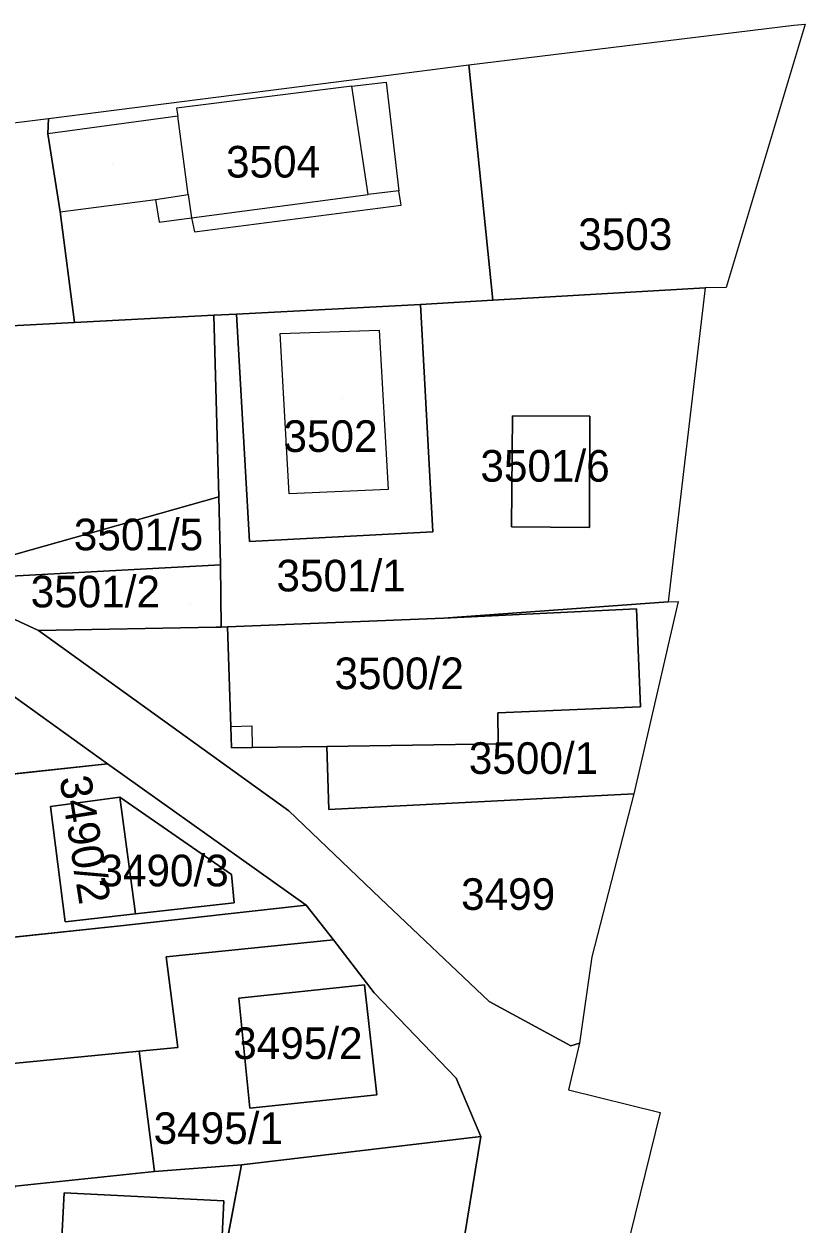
# Model space of a CAD drawing. Extents: x -262657 to -261595, y -1238015 to -1237156.
# Drawn here: x -262117.9 to -262068.5, y -1237493.9 to -1237418 of the extents above; entities that cross this region are included whole.
import ezdxf

# ---------------------------------------------------------------- set-up
doc = ezdxf.new("R2010")
doc.units = 0
for name, color, linetype in [('body_kn', 7, 'Continuous'), ('kladpar_druhypozemkov', 7, 'Continuous'), ('kladpar_hranice', 7, 'Continuous'), ('kladpar_parcelnecisla', 7, 'Continuous'), ('kladpar_plochy', 7, 'Continuous'), ('zappar_hrandruhpozemk', 7, 'Continuous')]:
    doc.layers.add(name, color=color, linetype=linetype)

msp = doc.modelspace()

# ---------------------------------------------------------------- linework, layer by layer
at = {"layer": 'body_kn'}
for p, q in [((-262069.23, -1237418.11), (-262069.23, -1237418.11)), ((-262068.53, -1237418.03), (-262068.53, -1237418.03)), ((-262090.13, -1237420.66), (-262090.13, -1237420.66)), ((-262089.8, -1237420.62), (-262089.8, -1237420.62)), ((-262089.8, -1237420.62), (-262089.8, -1237420.62)), ((-262095.05, -1237421.28), (-262095.05, -1237421.28)), ((-262097.19, -1237421.97), (-262097.19, -1237421.97)), ((-262097.19, -1237421.97), (-262097.19, -1237421.97)), ((-262095.02, -1237421.7), (-262095.02, -1237421.7)), ((-262108.29, -1237423.36), (-262108.29, -1237423.36)), ((-262116.37, -1237424), (-262116.37, -1237424)), ((-262108.2, -1237423.86), (-262108.2, -1237423.86)), ((-262116.41, -1237424.98), (-262116.41, -1237424.98)), ((-262107.54, -1237428.82), (-262107.54, -1237428.82)), ((-262107.54, -1237428.82), (-262107.54, -1237428.82)), ((-262096.16, -1237428.82), (-262096.16, -1237428.82)), ((-262096.16, -1237428.82), (-262096.16, -1237428.82)), ((-262094.21, -1237428.57), (-262094.21, -1237428.57)), ((-262109.62, -1237429.12), (-262109.62, -1237429.12)), ((-262109.62, -1237429.12), (-262109.62, -1237429.12)), ((-262094.07, -1237429.48), (-262094.07, -1237429.48)), ((-262115.63, -1237429.9), (-262115.63, -1237429.9)), ((-262115.63, -1237429.9), (-262115.63, -1237429.9)), ((-262109.37, -1237430.57), (-262109.37, -1237430.57)), ((-262107.34, -1237430.29), (-262107.34, -1237430.29)), ((-262107.34, -1237430.29), (-262107.34, -1237430.29)), ((-262107.15, -1237431.18), (-262107.15, -1237431.18)), ((-262074.85, -1237434.72), (-262074.85, -1237434.72)), ((-262073.52, -1237434.7), (-262073.52, -1237434.7)), ((-262092.84, -1237435.77), (-262092.84, -1237435.77)), ((-262092.84, -1237435.77), (-262092.84, -1237435.77)), ((-262088.28, -1237435.49), (-262088.28, -1237435.49)), ((-262105.91, -1237436.45), (-262105.91, -1237436.45)), ((-262104.48, -1237436.37), (-262104.48, -1237436.37)), ((-262114.74, -1237436.9), (-262114.74, -1237436.9)), ((-262095.46, -1237437.4), (-262095.46, -1237437.4)), ((-262101.73, -1237437.61), (-262101.73, -1237437.61)), ((-262101.73, -1237437.61), (-262101.73, -1237437.61)), ((-262087.04, -1237442.8), (-262087.04, -1237442.8)), ((-262087.04, -1237442.8), (-262087.04, -1237442.8)), ((-262082.14, -1237442.83), (-262082.14, -1237442.83)), ((-262105.6, -1237447.92), (-262105.6, -1237447.92)), ((-262101.16, -1237447.74), (-262101.16, -1237447.74)), ((-262094.9, -1237447.46), (-262094.9, -1237447.46)), ((-262092.06, -1237450.15), (-262092.06, -1237450.15)), ((-262087.09, -1237449.83), (-262087.09, -1237449.83)), ((-262082.17, -1237449.86), (-262082.17, -1237449.86)), ((-262103.67, -1237450.75), (-262103.67, -1237450.75)), ((-262105.49, -1237452.24), (-262105.49, -1237452.24)), ((-262077.18, -1237454.57), (-262077.18, -1237454.57)), ((-262077.18, -1237454.57), (-262077.18, -1237454.57)), ((-262076.55, -1237454.54), (-262076.55, -1237454.54)), ((-262091.39, -1237455.6), (-262091.39, -1237455.6)), ((-262079.19, -1237455.01), (-262079.19, -1237455.01)), ((-262117.01, -1237456.38), (-262117.01, -1237456.38)), ((-262117.01, -1237456.38), (-262117.01, -1237456.38)), ((-262105.78, -1237456.17), (-262105.78, -1237456.17)), ((-262105.45, -1237456.17), (-262105.45, -1237456.17)), ((-262105.06, -1237456.15), (-262105.06, -1237456.15)), ((-262105.06, -1237456.15), (-262105.06, -1237456.15)), ((-262087.96, -1237461.59), (-262087.96, -1237461.59)), ((-262078.94, -1237461.21), (-262078.94, -1237461.21)), ((-262104.85, -1237462.46), (-262104.85, -1237462.46)), ((-262104.85, -1237462.46), (-262104.85, -1237462.46)), ((-262103.52, -1237462.42), (-262103.52, -1237462.42)), ((-262104.81, -1237463.8), (-262104.81, -1237463.8)), ((-262103.5, -1237463.78), (-262103.5, -1237463.78)), ((-262098.78, -1237463.71), (-262098.78, -1237463.71)), ((-262087.93, -1237463.54), (-262087.93, -1237463.54)), ((-262112.65, -1237464.82), (-262112.65, -1237464.82)), ((-262111.86, -1237466.92), (-262111.86, -1237466.92)), ((-262111.86, -1237466.92), (-262111.86, -1237466.92)), ((-262079.35, -1237466.7), (-262079.35, -1237466.7)), ((-262079.35, -1237466.7), (-262079.35, -1237466.7)), ((-262116.25, -1237467.51), (-262116.25, -1237467.51)), ((-262116.25, -1237467.51), (-262116.25, -1237467.51)), ((-262098.64, -1237467.71), (-262098.64, -1237467.71)), ((-262101.17, -1237467.78), (-262101.17, -1237467.78)), ((-262104.81, -1237471.82), (-262104.81, -1237471.82)), ((-262104.63, -1237473.6), (-262104.63, -1237473.6)), ((-262100.07, -1237473.74), (-262100.07, -1237473.74)), ((-262100.07, -1237473.74), (-262100.07, -1237473.74)), ((-262095.4, -1237473.3), (-262095.4, -1237473.3)), ((-262110.87, -1237474.3), (-262110.87, -1237474.3)), ((-262115.33, -1237474.8), (-262115.33, -1237474.8)), ((-262111.63, -1237475.04), (-262111.63, -1237475.04)), ((-262098.36, -1237475.95), (-262098.36, -1237475.95)), ((-262098.36, -1237475.95), (-262098.36, -1237475.95)), ((-262108.93, -1237477.01), (-262108.93, -1237477.01)), ((-262082.01, -1237477.02), (-262082.01, -1237477.02)), ((-262096.39, -1237478.78), (-262096.39, -1237478.78)), ((-262104.34, -1237479.64), (-262104.34, -1237479.64)), ((-262095.77, -1237479.3), (-262095.77, -1237479.3)), ((-262088.51, -1237479.84), (-262088.51, -1237479.84)), ((-262108.19, -1237482.75), (-262108.19, -1237482.75)), ((-262083.34, -1237482.64), (-262083.34, -1237482.64)), ((-262082.79, -1237482.48), (-262082.79, -1237482.48)), ((-262110.64, -1237482.99), (-262110.64, -1237482.99)), ((-262110.64, -1237482.99), (-262110.64, -1237482.99)), ((-262090.6, -1237484.7), (-262090.6, -1237484.7)), ((-262095.61, -1237485.75), (-262095.61, -1237485.75)), ((-262083.48, -1237485.42), (-262083.48, -1237485.42)), ((-262103.64, -1237486.58), (-262103.64, -1237486.58)), ((-262103.64, -1237486.58), (-262103.64, -1237486.58)), ((-262077.7, -1237486.87), (-262077.7, -1237486.87)), ((-262089.04, -1237488.37), (-262089.04, -1237488.37)), ((-262104.18, -1237490.18), (-262104.18, -1237490.18)), ((-262109.68, -1237490.6), (-262109.68, -1237490.6)), ((-262115.39, -1237491.95), (-262115.39, -1237491.95)), ((-262115.39, -1237491.95), (-262115.39, -1237491.95)), ((-262105.28, -1237492.44), (-262105.28, -1237492.44)), ((-262079.28, -1237493.28), (-262079.28, -1237493.28))]:
    msp.add_line(p, q, dxfattribs=at)
at = {"layer": 'kladpar_druhypozemkov'}
for p, q in [((-262102.06, -1237425.79), (-262102.06, -1237425.79)), ((-262112.32, -1237426.86), (-262112.32, -1237426.86)), ((-262079.63, -1237430.09), (-262079.63, -1237430.09)), ((-262097.78, -1237441.71), (-262097.78, -1237441.71)), ((-262084.64, -1237445.3), (-262084.64, -1237445.3)), ((-262107.55, -1237449.98), (-262107.55, -1237449.98)), ((-262098.05, -1237452.19), (-262098.05, -1237452.19)), ((-262107.4, -1237454.65), (-262107.4, -1237454.65)), ((-262093, -1237457.72), (-262093, -1237457.72)), ((-262084.88, -1237463.58), (-262084.88, -1237463.58)), ((-262113.06, -1237470.35), (-262113.06, -1237470.35)), ((-262108.54, -1237470.73), (-262108.54, -1237470.73)), ((-262087.23, -1237472.24), (-262087.23, -1237472.24)), ((-262099.72, -1237482.04), (-262099.72, -1237482.04)), ((-262105.41, -1237486.92), (-262105.41, -1237486.92))]:
    msp.add_line(p, q, dxfattribs=at)
at = {"layer": 'kladpar_hranice'}
for points in [[(-262089.8, -1237420.62), (-262069.23, -1237418.11), (-262068.53, -1237418.03), (-262073.52, -1237434.7), (-262074.85, -1237434.72), (-262088.28, -1237435.49), (-262089.8, -1237420.62)], [(-262092.84, -1237435.77), (-262104.48, -1237436.37), (-262105.91, -1237436.45), (-262114.74, -1237436.9), (-262115.63, -1237429.9), (-262116.41, -1237424.98), (-262116.37, -1237424), (-262095.05, -1237421.28), (-262090.13, -1237420.66), (-262089.8, -1237420.62), (-262088.28, -1237435.49), (-262092.84, -1237435.77)], [(-262173.41, -1237431.09), (-262116.37, -1237424), (-262116.41, -1237424.98), (-262115.63, -1237429.9), (-262114.74, -1237436.9), (-262145.51, -1237438.52), (-262171.89, -1237439.97), (-262172.3, -1237439.99), (-262173.41, -1237431.09)], [(-262074.85, -1237434.72), (-262077.18, -1237454.57), (-262091.39, -1237455.6), (-262105.06, -1237456.15), (-262105.45, -1237456.17), (-262105.49, -1237452.24), (-262105.6, -1237447.92), (-262105.91, -1237436.45), (-262104.48, -1237436.37), (-262103.67, -1237450.75), (-262092.06, -1237450.15), (-262092.84, -1237435.77)], [(-262092.84, -1237435.77), (-262088.28, -1237435.49), (-262074.85, -1237434.72)], [(-262092.84, -1237435.77), (-262092.06, -1237450.15), (-262103.67, -1237450.75), (-262104.48, -1237436.37), (-262092.84, -1237435.77)], [(-262133.73, -1237451.77), (-262144.2, -1237451.94), (-262145.51, -1237438.52), (-262114.74, -1237436.9), (-262105.91, -1237436.45), (-262105.6, -1237447.92), (-262118.45, -1237451.55), (-262133.73, -1237451.77)], [(-262087.04, -1237442.8), (-262082.14, -1237442.83), (-262082.17, -1237449.86), (-262087.09, -1237449.83), (-262087.04, -1237442.8)], [(-262082.14, -1237442.83), (-262087.04, -1237442.8), (-262087.09, -1237449.83), (-262082.17, -1237449.86), (-262082.14, -1237442.83)], [(-262123.85, -1237453.21), (-262133.73, -1237451.77), (-262118.45, -1237451.55), (-262105.6, -1237447.92), (-262105.49, -1237452.24), (-262123.85, -1237453.21)], [(-262172.23, -1237452.72), (-262144.2, -1237451.94), (-262133.73, -1237451.77), (-262123.85, -1237453.21), (-262117.01, -1237456.38), (-262101.17, -1237467.78), (-262095.4, -1237473.3), (-262088.51, -1237479.84), (-262083.34, -1237482.64), (-262082.79, -1237482.48), (-262083.48, -1237485.42), (-262077.7, -1237486.87), (-262079.28, -1237493.28), (-262079.83, -1237495.53)], [(-262117.01, -1237456.38), (-262123.85, -1237453.21), (-262105.49, -1237452.24), (-262105.45, -1237456.17), (-262105.78, -1237456.17), (-262117.01, -1237456.38)], [(-262077.18, -1237454.57), (-262076.55, -1237454.54), (-262079.35, -1237466.7), (-262098.64, -1237467.71), (-262098.78, -1237463.71), (-262087.93, -1237463.54), (-262087.96, -1237461.59), (-262078.94, -1237461.21), (-262079.19, -1237455.01), (-262091.39, -1237455.6), (-262077.18, -1237454.57)], [(-262090.96, -1237500.11), (-262089.04, -1237488.37), (-262090.6, -1237484.7), (-262095.77, -1237479.3), (-262098.36, -1237475.95), (-262100.07, -1237473.74), (-262112.65, -1237464.82), (-262118.96, -1237460.26), (-262120.3, -1237459.49), (-262124.74, -1237457.28), (-262137.3, -1237455.41), (-262166.33, -1237456.32)], [(-262105.06, -1237456.15), (-262091.39, -1237455.6), (-262079.19, -1237455.01), (-262078.94, -1237461.21), (-262087.96, -1237461.59), (-262087.93, -1237463.54), (-262098.78, -1237463.71), (-262103.5, -1237463.78), (-262104.81, -1237463.8), (-262104.85, -1237462.46), (-262105.06, -1237456.15)], [(-262079.35, -1237466.7), (-262082.01, -1237477.02), (-262082.79, -1237482.48), (-262083.34, -1237482.64), (-262088.51, -1237479.84), (-262095.4, -1237473.3), (-262101.17, -1237467.78), (-262117.01, -1237456.38), (-262105.78, -1237456.17), (-262105.45, -1237456.17), (-262105.06, -1237456.15), (-262104.85, -1237462.46), (-262104.81, -1237463.8), (-262103.5, -1237463.78), (-262098.78, -1237463.71), (-262098.64, -1237467.71), (-262079.35, -1237466.7)], [(-262143.93, -1237461.51), (-262120.3, -1237459.49), (-262118.96, -1237460.26), (-262112.65, -1237464.82), (-262128.64, -1237466.53), (-262127.67, -1237476.36), (-262127.63, -1237476.72), (-262135.5, -1237477.53), (-262135.51, -1237477.18), (-262135.55, -1237475.84), (-262137.27, -1237475.95), (-262138.13, -1237467.57), (-262143.12, -1237468.01), (-262143.93, -1237461.51)], [(-262128.64, -1237466.53), (-262112.65, -1237464.82), (-262100.07, -1237473.74)], [(-262100.07, -1237473.74), (-262111.63, -1237475.04), (-262121.33, -1237476.07), (-262127.63, -1237476.72), (-262127.67, -1237476.36), (-262128.64, -1237466.53)], [(-262116.25, -1237467.51), (-262111.86, -1237466.92), (-262110.87, -1237474.3), (-262115.33, -1237474.8), (-262116.25, -1237467.51)], [(-262116.25, -1237467.51), (-262115.33, -1237474.8), (-262110.87, -1237474.3), (-262104.63, -1237473.6), (-262104.81, -1237471.82), (-262111.86, -1237466.92), (-262116.25, -1237467.51)], [(-262111.86, -1237466.92), (-262104.81, -1237471.82), (-262104.63, -1237473.6), (-262110.87, -1237474.3), (-262111.86, -1237466.92)], [(-262100.07, -1237473.74), (-262098.36, -1237475.95), (-262108.93, -1237477.01), (-262108.19, -1237482.75), (-262110.64, -1237482.99), (-262139.61, -1237485.8), (-262139.74, -1237483.44), (-262150.33, -1237484.6), (-262162.65, -1237485.9), (-262172.82, -1237486.91), (-262173.3, -1237481.5), (-262167.76, -1237480.98), (-262159, -1237480.03), (-262135.5, -1237477.53), (-262127.63, -1237476.72), (-262121.33, -1237476.07), (-262111.63, -1237475.04), (-262100.07, -1237473.74)], [(-262098.36, -1237475.95), (-262095.77, -1237479.3), (-262090.6, -1237484.7), (-262089.04, -1237488.37), (-262104.18, -1237490.18), (-262109.68, -1237490.6), (-262110.64, -1237482.99), (-262108.19, -1237482.75), (-262108.93, -1237477.01), (-262098.36, -1237475.95)], [(-262104.34, -1237479.64), (-262103.64, -1237486.58), (-262095.61, -1237485.75), (-262096.39, -1237478.78), (-262104.34, -1237479.64)], [(-262103.64, -1237486.58), (-262104.34, -1237479.64), (-262096.39, -1237478.78), (-262095.61, -1237485.75), (-262103.64, -1237486.58)], [(-262110.64, -1237482.99), (-262109.68, -1237490.6), (-262118.48, -1237491.51), (-262139.16, -1237493.69), (-262139.61, -1237485.8), (-262110.64, -1237482.99)], [(-262108.51, -1237513.15), (-262103.86, -1237514), (-262102.51, -1237505.33), (-262106.86, -1237504.51), (-262105.52, -1237497.34), (-262104.18, -1237490.18), (-262089.04, -1237488.37), (-262090.96, -1237500.11), (-262096.16, -1237518.4)], [(-262108.89, -1237515.33), (-262123.16, -1237511.93), (-262118.48, -1237491.51), (-262109.68, -1237490.6), (-262104.18, -1237490.18), (-262105.52, -1237497.34), (-262105.28, -1237492.44), (-262115.39, -1237491.95), (-262115.63, -1237496.84), (-262105.52, -1237497.34), (-262106.86, -1237504.51), (-262108.51, -1237513.15), (-262108.89, -1237515.33)], [(-262115.39, -1237491.95), (-262105.28, -1237492.44), (-262105.52, -1237497.34), (-262115.63, -1237496.84), (-262115.39, -1237491.95)]]:
    msp.add_lwpolyline(points, dxfattribs=at)
at = {"layer": 'kladpar_plochy'}
for p, q in [((-262088.28, -1237435.49), (-262074.85, -1237434.72)), ((-262074.85, -1237434.72), (-262077.18, -1237454.57)), ((-262092.84, -1237435.77), (-262088.28, -1237435.49)), ((-262092.06, -1237450.15), (-262092.84, -1237435.77)), ((-262105.91, -1237436.45), (-262104.48, -1237436.37)), ((-262105.6, -1237447.92), (-262105.91, -1237436.45)), ((-262104.48, -1237436.37), (-262103.67, -1237450.75)), ((-262087.04, -1237442.8), (-262087.09, -1237449.83)), ((-262082.14, -1237442.83), (-262087.04, -1237442.8)), ((-262082.17, -1237449.86), (-262082.14, -1237442.83)), ((-262105.49, -1237452.24), (-262105.6, -1237447.92)), ((-262103.67, -1237450.75), (-262092.06, -1237450.15)), ((-262087.09, -1237449.83), (-262082.17, -1237449.86)), ((-262105.45, -1237456.17), (-262105.49, -1237452.24)), ((-262077.18, -1237454.57), (-262091.39, -1237455.6)), ((-262091.39, -1237455.6), (-262105.06, -1237456.15)), ((-262105.06, -1237456.15), (-262105.45, -1237456.17)), ((-262128.64, -1237466.53), (-262112.65, -1237464.82)), ((-262112.65, -1237464.82), (-262100.07, -1237473.74)), ((-262111.86, -1237466.92), (-262116.25, -1237467.51)), ((-262104.81, -1237471.82), (-262111.86, -1237466.92)), ((-262116.25, -1237467.51), (-262115.33, -1237474.8)), ((-262104.63, -1237473.6), (-262104.81, -1237471.82)), ((-262100.07, -1237473.74), (-262111.63, -1237475.04)), ((-262110.87, -1237474.3), (-262104.63, -1237473.6)), ((-262115.33, -1237474.8), (-262110.87, -1237474.3)), ((-262111.63, -1237475.04), (-262121.33, -1237476.07)), ((-262108.93, -1237477.01), (-262098.36, -1237475.95)), ((-262098.36, -1237475.95), (-262095.77, -1237479.3)), ((-262108.19, -1237482.75), (-262108.93, -1237477.01)), ((-262096.39, -1237478.78), (-262104.34, -1237479.64)), ((-262095.61, -1237485.75), (-262096.39, -1237478.78)), ((-262104.34, -1237479.64), (-262103.64, -1237486.58)), ((-262095.77, -1237479.3), (-262090.6, -1237484.7)), ((-262110.64, -1237482.99), (-262108.19, -1237482.75)), ((-262109.68, -1237490.6), (-262110.64, -1237482.99)), ((-262090.6, -1237484.7), (-262089.04, -1237488.37)), ((-262103.64, -1237486.58), (-262095.61, -1237485.75)), ((-262104.18, -1237490.18), (-262089.04, -1237488.37)), ((-262089.04, -1237488.37), (-262104.18, -1237490.18)), ((-262089.04, -1237488.37), (-262090.96, -1237500.11)), ((-262104.18, -1237490.18), (-262109.68, -1237490.6)), ((-262105.52, -1237497.34), (-262104.18, -1237490.18))]:
    msp.add_line(p, q, dxfattribs=at)
for points in [[(-262089.8, -1237420.62), (-262069.23, -1237418.11), (-262068.53, -1237418.03), (-262073.52, -1237434.7), (-262074.85, -1237434.72), (-262088.28, -1237435.49)], [(-262092.84, -1237435.77), (-262104.48, -1237436.37), (-262105.91, -1237436.45), (-262114.74, -1237436.9), (-262115.63, -1237429.9), (-262116.41, -1237424.98), (-262116.37, -1237424), (-262095.05, -1237421.28), (-262090.13, -1237420.66), (-262089.8, -1237420.62), (-262088.28, -1237435.49)], [(-262173.41, -1237431.09), (-262116.37, -1237424), (-262116.41, -1237424.98), (-262115.63, -1237429.9), (-262114.74, -1237436.9), (-262145.51, -1237438.52), (-262171.89, -1237439.97), (-262172.3, -1237439.99)], [(-262092.84, -1237435.77), (-262092.06, -1237450.15), (-262103.67, -1237450.75), (-262104.48, -1237436.37)], [(-262133.73, -1237451.77), (-262144.2, -1237451.94), (-262145.51, -1237438.52), (-262114.74, -1237436.9), (-262105.91, -1237436.45), (-262105.6, -1237447.92), (-262118.45, -1237451.55)], [(-262087.04, -1237442.8), (-262082.14, -1237442.83), (-262082.17, -1237449.86), (-262087.09, -1237449.83)], [(-262123.85, -1237453.21), (-262133.73, -1237451.77), (-262118.45, -1237451.55), (-262105.6, -1237447.92), (-262105.49, -1237452.24)], [(-262117.01, -1237456.38), (-262123.85, -1237453.21), (-262105.49, -1237452.24), (-262105.45, -1237456.17), (-262105.78, -1237456.17)], [(-262077.18, -1237454.57), (-262076.55, -1237454.54), (-262079.35, -1237466.7), (-262098.64, -1237467.71), (-262098.78, -1237463.71), (-262087.93, -1237463.54), (-262087.96, -1237461.59), (-262078.94, -1237461.21), (-262079.19, -1237455.01), (-262091.39, -1237455.6)], [(-262105.06, -1237456.15), (-262091.39, -1237455.6), (-262079.19, -1237455.01), (-262078.94, -1237461.21), (-262087.96, -1237461.59), (-262087.93, -1237463.54), (-262098.78, -1237463.71), (-262103.5, -1237463.78), (-262104.81, -1237463.8), (-262104.85, -1237462.46)], [(-262079.35, -1237466.7), (-262082.01, -1237477.02), (-262082.79, -1237482.48), (-262083.34, -1237482.64), (-262088.51, -1237479.84), (-262095.4, -1237473.3), (-262101.17, -1237467.78), (-262117.01, -1237456.38), (-262105.78, -1237456.17), (-262105.45, -1237456.17), (-262105.06, -1237456.15), (-262104.85, -1237462.46), (-262104.81, -1237463.8), (-262103.5, -1237463.78), (-262098.78, -1237463.71), (-262098.64, -1237467.71)], [(-262143.93, -1237461.51), (-262120.3, -1237459.49), (-262118.96, -1237460.26), (-262112.65, -1237464.82), (-262128.64, -1237466.53), (-262127.67, -1237476.36), (-262127.63, -1237476.72), (-262135.5, -1237477.53), (-262135.51, -1237477.18), (-262135.55, -1237475.84), (-262137.27, -1237475.95), (-262138.13, -1237467.57), (-262143.12, -1237468.01)], [(-262116.25, -1237467.51), (-262111.86, -1237466.92), (-262110.87, -1237474.3), (-262115.33, -1237474.8)], [(-262111.86, -1237466.92), (-262104.81, -1237471.82), (-262104.63, -1237473.6), (-262110.87, -1237474.3)], [(-262100.07, -1237473.74), (-262098.36, -1237475.95), (-262108.93, -1237477.01), (-262108.19, -1237482.75), (-262110.64, -1237482.99), (-262139.61, -1237485.8), (-262139.74, -1237483.44), (-262150.33, -1237484.6), (-262162.65, -1237485.9), (-262172.82, -1237486.91), (-262173.3, -1237481.5), (-262167.76, -1237480.98), (-262159, -1237480.03), (-262135.5, -1237477.53), (-262127.63, -1237476.72), (-262121.33, -1237476.07), (-262111.63, -1237475.04)], [(-262103.64, -1237486.58), (-262104.34, -1237479.64), (-262096.39, -1237478.78), (-262095.61, -1237485.75)], [(-262110.64, -1237482.99), (-262109.68, -1237490.6), (-262118.48, -1237491.51), (-262139.16, -1237493.69), (-262139.61, -1237485.8)], [(-262108.89, -1237515.33), (-262123.16, -1237511.93), (-262118.48, -1237491.51), (-262109.68, -1237490.6), (-262104.18, -1237490.18), (-262105.52, -1237497.34), (-262105.28, -1237492.44), (-262115.39, -1237491.95), (-262115.63, -1237496.84), (-262105.52, -1237497.34), (-262106.86, -1237504.51), (-262108.51, -1237513.15)], [(-262115.39, -1237491.95), (-262105.28, -1237492.44), (-262105.52, -1237497.34), (-262115.63, -1237496.84)]]:
    msp.add_lwpolyline(points, close=True, dxfattribs=at)
for points in [[(-262172.23, -1237452.72), (-262144.2, -1237451.94), (-262133.73, -1237451.77), (-262123.85, -1237453.21), (-262117.01, -1237456.38), (-262101.17, -1237467.78), (-262095.4, -1237473.3), (-262088.51, -1237479.84), (-262083.34, -1237482.64), (-262082.79, -1237482.48), (-262083.48, -1237485.42), (-262077.7, -1237486.87), (-262079.28, -1237493.28), (-262079.83, -1237495.53)], [(-262090.96, -1237500.11), (-262089.04, -1237488.37), (-262090.6, -1237484.7), (-262095.77, -1237479.3), (-262098.36, -1237475.95), (-262100.07, -1237473.74), (-262112.65, -1237464.82), (-262118.96, -1237460.26), (-262120.3, -1237459.49), (-262124.74, -1237457.28), (-262137.3, -1237455.41), (-262166.33, -1237456.32)]]:
    msp.add_lwpolyline(points, dxfattribs=at)
at = {"layer": 'zappar_hrandruhpozemk'}
for p, q in [((-262097.19, -1237421.97), (-262095.02, -1237421.7)), ((-262096.16, -1237428.82), (-262097.19, -1237421.97)), ((-262095.02, -1237421.7), (-262094.21, -1237428.57)), ((-262107.54, -1237428.82), (-262107.34, -1237430.29)), ((-262107.34, -1237430.29), (-262096.16, -1237428.82)), ((-262107.15, -1237431.18), (-262094.07, -1237429.48)), ((-262101.16, -1237447.74), (-262101.73, -1237437.61)), ((-262094.9, -1237447.46), (-262101.16, -1237447.74))]:
    msp.add_line(p, q, dxfattribs=at)
for points in [[(-262097.19, -1237421.97), (-262108.29, -1237423.36), (-262108.2, -1237423.86), (-262116.41, -1237424.98)], [(-262109.62, -1237429.12), (-262107.54, -1237428.82), (-262108.2, -1237423.86)], [(-262094.07, -1237429.48), (-262094.21, -1237428.57), (-262096.16, -1237428.82)], [(-262115.63, -1237429.9), (-262109.62, -1237429.12), (-262109.37, -1237430.57), (-262107.34, -1237430.29), (-262107.15, -1237431.18)], [(-262101.73, -1237437.61), (-262095.46, -1237437.4), (-262094.9, -1237447.46)], [(-262104.85, -1237462.46), (-262103.52, -1237462.42), (-262103.5, -1237463.78)]]:
    msp.add_lwpolyline(points, dxfattribs=at)

# ---------------------------------------------------------------- texts
at = {"layer": 'kladpar_parcelnecisla'}
for s, p in [('3504', (-262105.149, -1237427.74)), ('3503', (-262082.871, -1237432.32)), ('3502', (-262101.516, -1237445.09)), ('3501/6', (-262089.06, -1237446.97)), ('3501/5', (-262114.775, -1237451.31)), ('3501/1', (-262101.96, -1237453.91)), ('3501/2', (-262117.506, -1237454.92)), ('3500/2', (-262098.287, -1237460.09)), ('3500/1', (-262089.791, -1237465.45)), ('3490/3', (-262113.156, -1237472.56)), ('3499', (-262090.282, -1237474.05))]:
    msp.add_text(s, height=2, dxfattribs=at).set_placement(p)
for s, rotation, p in [('3490/2', 279, (-262115.691, -1237465.708)), ('3495/2', 360, (-262104.694, -1237483.48)), ('3495/1', 360, (-262109.728, -1237488.85))]:
    msp.add_text(s, height=2, rotation=rotation, dxfattribs=at).set_placement(p)

doc.saveas('drawing.dxf')
